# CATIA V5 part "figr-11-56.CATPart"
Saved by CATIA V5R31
Part number: Part1
Bounding box of the stored display mesh (mm): x -50 to 50, y -100 to 150, z -20 to 9.95
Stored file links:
  D:\PROJECTS\Project 2021\US EDITION\CATIA V5 6R 2021\Resources\Part Files\c11_catia_v5_6r2021_prt\figr-11-56.CATPart
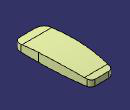
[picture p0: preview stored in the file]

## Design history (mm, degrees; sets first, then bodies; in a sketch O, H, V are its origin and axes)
Set1
  Extrude1: Element1 Sketch2, Lim1 50, Lim2 50, Direction yz-plane
  Sketch1 on xy-plane, origin (0, 0, 0), H (1, 0, 0), V (0, 1, 0)
    arc A1 centre (25, -75) radius 25 from (25, -100) to (50, -75) ccw
    line L1 (50, -75) -> (50, -15)
    point P4 (50, -15)
    arc A2 centre (-950, -15) radius 1000 from (50, -15) to (38.3367, 137.2843) ccw
    line L2 (23.5117, 150) -> (-23.5117, 150)
    line L3 (25, -100) -> (-25, -100)
    arc A3 centre (-25, -75) radius 25 from (-25, -100) to (-50, -75) cw
    line L4 (-50, -75) -> (-50, -15)
    point P9 (-50, -15)
    arc A4 centre (950, -15) radius 1000 from (-50, -15) to (-38.3367, 137.2843) cw
    reference projected line E1 (-50, -100) -> (50, -100) from edge of Extrude1
    axis line L5 (0, 170.4214) -> (0, -120.6595)
    point P11 (0, 170.4214)
    reference projected line E2 (50, -70) -> (50, 129.9971) from edge of Extrude1
    reference projected line E3 (-50, 129.9971) -> (-50, -70) from edge of Extrude1
    reference projected line E4 (-50, -100) -> (50, -100) from edge of Extrude1
    reference projected line E5 (50, 150) -> (-50, 150) from edge of Extrude1
    arc A5 centre (-23.5117, 135) radius 15 from (-38.3367, 137.2843) to (-23.5117, 150) cw
    arc A6 centre (23.5117, 135) radius 15 from (38.3367, 137.2843) to (23.5117, 150) ccw
    distance E4 P4 = 85
    radius A2 = 1000
    radius A5 = 15
    radius A6 = 15
    radius A1 = 25
    radius A3 = 25
    radius A4 = 1000
    tangency: L1 A1, A2 L1, L3 A1, A3 L3, A4 L4, L5 A3, A5 L2, A5 A4, A6 A2, A6 L2, A3 L4
    horizontal: L2 H
    coincidence: L3 E1, P11 V, L1 E2, L4 E3, L2 E5
    symmetry: P4 P9 L5
  Extrude2: Element1 Sketch1, Lim1 50, Lim2 20, Direction xy-plane
  Intersect1: ToIntersect1 Extrude1, ToIntersect2 Extrude2
  Split1: ToCut Extrude2, Cutting Extrude1
  Trim1: Trimmed (Extrude1; Split1)
Body1 (main body)
  Sketch2 on yz-plane, origin (0, 0, 0), H (0, 1, 0), V (0, 0, 1)
    point P1 (-100, 0)
    line L1 (-100, 0) -> (-70, 3.8724)
    point P2 (-70, 3.8724)
    arc A1 centre (26.0141, -739.9564) radius 750 from (-70, 3.8724) to (129.9971, 2.8003) cw
    point P4 (129.9971, 2.8003)
    line L2 (129.9971, 2.8003) -> (150, 0)
    point P5 (150, 0)
    distance P1 P5 = 250
    distance P1 O = 100
    radius A1 = 750
    distance P2 P4 = 200
    distance P2 V = 70
    coincidence: P1 H, P5 H
    tangency: A1 L1, L2 A1
  ThickSurface1: BotOffset 0, Surface Extrude1, TopOffset 5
